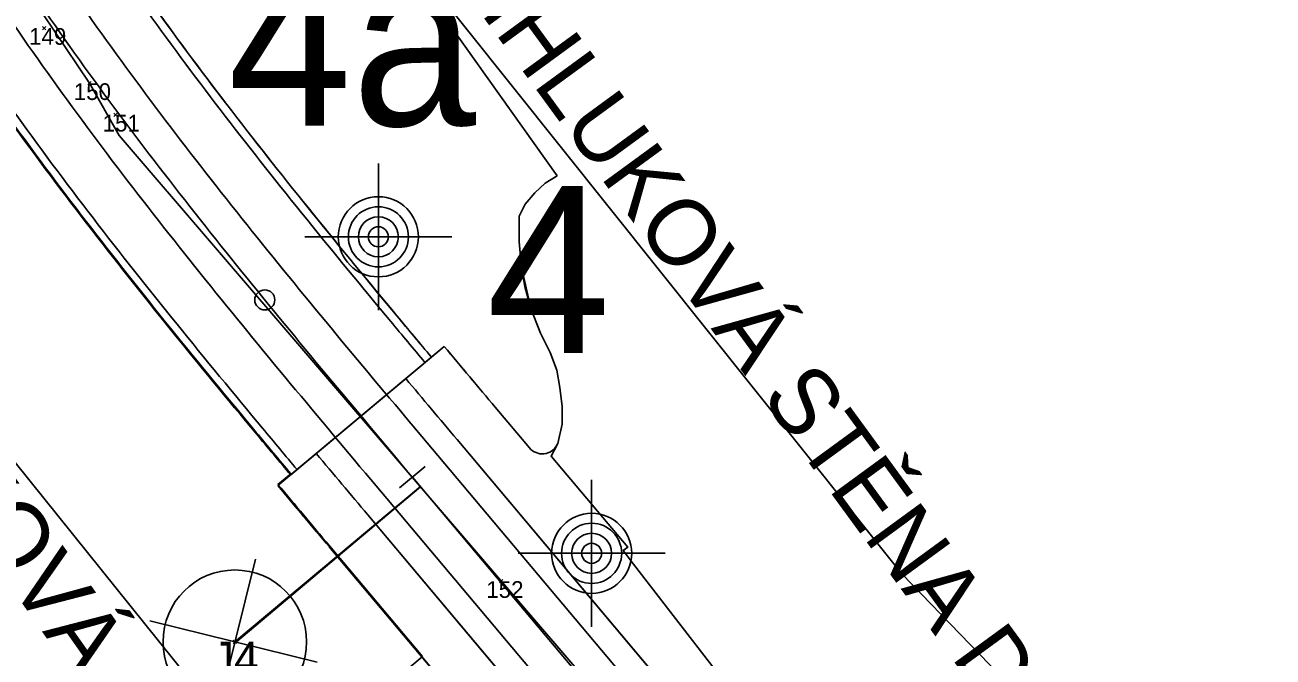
# Model space of a CAD drawing. Extents: x -606444 to -604546, y -1158114 to -1156869.
# Drawn here: x -605089.5 to -605014.7, y -1157408.3 to -1157370.5 of the extents above; entities that cross this region are included whole.
import ezdxf

# ---------------------------------------------------------------- set-up
doc = ezdxf.new("R2010")
doc.units = 0
for name, color, linetype in [('0_sondy', 7, 'Continuous'), ('B_CHOD', 7, 'Continuous'), ('B_TRAM', 7, 'Continuous'), ('B_ZELEN', 7, 'Continuous'), ('geofyzikální profily_předběžný GTP', 7, 'Continuous'), ('jádrové vrty_předběžný GTP', 7, 'Continuous'), ('netisk', 7, 'Continuous'), ('netisk2', 7, 'Continuous'), ('NS_VB', 7, 'Continuous'), ('NS_VB_OBJ', 7, 'Continuous'), ('NS_VB_POP', 7, 'Continuous'), ('OSA', 7, 'Continuous'), ('OSAPOP', 7, 'Continuous'), ('podélný profil trasou tramvaje', 7, 'Continuous'), ('Sondy 2', 7, 'Continuous'), ('sondy současného průzkumu', 7, 'Continuous')]:
    doc.layers.add(name, color=color, linetype=linetype)

# ---------------------------------------------------------------- blocks, each defined once
blk = doc.blocks.new('709')
for p, q in [((0, 2.2), (0, -2.2)), ((-2.2, 0), (2.2, 0))]:
    blk.add_line(p, q)
for radius in [1.2, 0.9, 0.6, 0.3]:
    blk.add_circle((0, 0), radius)
blk = doc.blocks.new('IG vrt podr')
at = {"layer": 'sondy současného průzkumu'}
for p, q in [((0.412, 1.649), (-0.418, -1.672)), ((-1.698, 0.422), (1.644, -0.408))]:
    blk.add_line(p, q, dxfattribs=at)
blk.add_circle((-0.002, 0.001), 1.434, dxfattribs=at)

msp = doc.modelspace()

# ---------------------------------------------------------------- linework, layer by layer
for p, q in [((-605088.39, -1157370.65), (-605088.49, -1157370.55)), ((-605088.39, -1157370.65), (-605088.49, -1157370.75)), ((-605088.39, -1157370.65), (-605088.29, -1157370.55)), ((-605088.39, -1157370.65), (-605088.29, -1157370.75)), ((-605085.67, -1157373.96), (-605085.77, -1157373.86)), ((-605085.67, -1157373.96), (-605085.77, -1157374.06)), ((-605085.67, -1157373.96), (-605085.57, -1157373.86)), ((-605085.67, -1157373.96), (-605085.57, -1157374.06)), ((-605084.1, -1157375.85), (-605084.2, -1157375.75)), ((-605084.1, -1157375.85), (-605084.2, -1157375.95)), ((-605084.1, -1157375.85), (-605084, -1157375.75)), ((-605084.1, -1157375.85), (-605084, -1157375.95)), ((-605060.98, -1157403.8), (-605061.08, -1157403.7)), ((-605060.98, -1157403.8), (-605061.08, -1157403.9)), ((-605060.98, -1157403.8), (-605060.88, -1157403.7)), ((-605060.98, -1157403.8), (-605060.88, -1157403.9)), ((-605076.949, -1157407.435), (-605077.049, -1157407.335)), ((-605076.949, -1157407.435), (-605077.049, -1157407.535)), ((-605076.949, -1157407.435), (-605076.849, -1157407.335)), ((-605076.949, -1157407.435), (-605076.849, -1157407.535))]:
    msp.add_line(p, q)
at = {"layer": 'B_CHOD'}
for points in [[(-605064.406, -1157389.728), (-605065.172, -1157390.37), (-605066.706, -1157391.654)], [(-605059.291, -1157395.814), (-605061.339, -1157393.379)], [(-605063.634, -1157395.311), (-605041.47, -1157421.663), (-605038.896, -1157424.722)], [(-605020.942, -1157444.312), (-605019.149, -1157442.695), (-605022.9, -1157438.91), (-605029, -1157432.1), (-605031.48, -1157429.37), (-605037.89, -1157421.92), (-605043.83, -1157414.58), (-605048.16, -1157409.11), (-605053.06, -1157402.78), (-605053.68, -1157401.97), (-605053.4, -1157401.77), (-605057.995, -1157396.306), (-605057.642, -1157395.638)], [(-605072.072, -1157396.149), (-605074.372, -1157398.075)], [(-605046.828, -1157426.168), (-605068.989, -1157399.819)], [(-605071.29, -1157401.745), (-605049.124, -1157428.099)]]:
    msp.add_lwpolyline(points, dxfattribs=at)
for centre, radius, start, end in [((-602183.251, -1154972.717), 3760.717, 219.993413, 220.066055), ((-603790.648, -1156322.905), 1664.496, 219.947524, 220.111903), ((-605058.526, -1157395.17), 1, 220.06606, 332.12726), ((-603790.638, -1156322.897), 1671.509, 219.947524, 220.111806), ((-603790.638, -1156322.897), 1674.509, 219.947537, 220.111495)]:
    msp.add_arc(centre, radius, start, end, dxfattribs=at)
at = {"layer": 'B_TRAM'}
for p, q in [((-605065.171, -1157390.369), (-605073.604, -1157397.432)), ((-605066.706, -1157391.654), (-605072.072, -1157396.149)), ((-605041.47, -1157421.663), (-605063.634, -1157395.311)), ((-605068.989, -1157399.819), (-605046.828, -1157426.168))]:
    msp.add_line(p, q, dxfattribs=at)
for centre, radius, start, end in [((-604901.683, -1157240.079), 221.711, 215.66934, 217.68438), ((-604798.339, -1157160.25), 352.296, 217.68438, 218.96694), ((-604901.683, -1157240.079), 232.711, 215.66934, 217.68438), ((-604798.339, -1157160.25), 363.296, 217.68438, 218.96694), ((-604687.845, -1157070.879), 494.409, 218.96694, 219.88278), ((-603150.695, -1155786.407), 2497.582, 219.882775, 219.956515), ((-604687.845, -1157070.879), 505.409, 218.96694, 219.88278), ((-603790.648, -1156322.905), 1664.496, 219.947524, 220.111903), ((-603150.695, -1155786.407), 2508.582, 219.882775, 219.956476), ((-603790.638, -1156322.897), 1671.509, 219.947524, 220.111806)]:
    msp.add_arc(centre, radius, start, end, dxfattribs=at)
at = {"layer": 'B_ZELEN'}
for p, q in [((-605067.868, -1157365.11), (-605057.63, -1157379.5)), ((-605058.34, -1157379.94), (-605058.97, -1157380.52)), ((-605057.63, -1157379.5), (-605058.34, -1157379.94)), ((-605058.97, -1157380.52), (-605059.54, -1157381.2)), ((-605059.54, -1157381.2), (-605059.9, -1157381.92)), ((-605059.9, -1157381.92), (-605059.91, -1157383.46)), ((-605059.91, -1157383.46), (-605059.77, -1157384.99)), ((-605059.77, -1157384.99), (-605059.2, -1157387.45)), ((-605059.2, -1157387.45), (-605058.63, -1157388.93)), ((-605058.63, -1157388.93), (-605058.05, -1157390.09)), ((-605064.406, -1157389.728), (-605065.172, -1157390.37)), ((-605058.05, -1157390.09), (-605057.66, -1157391.16)), ((-605057.66, -1157391.16), (-605057.48, -1157392.2)), ((-605057.48, -1157392.2), (-605057.34, -1157393.34)), ((-605059.291, -1157395.814), (-605061.339, -1157393.379)), ((-605057.34, -1157393.34), (-605057.33, -1157394.38)), ((-605057.33, -1157394.38), (-605057.59, -1157395.54)), ((-605057.59, -1157395.54), (-605057.642, -1157395.638)), ((-605073.604, -1157397.358), (-605074.371, -1157398)), ((-605071.284, -1157401.676), (-605065.705, -1157408.309)), ((-605065.705, -1157408.309), (-605068.192, -1157410.401))]:
    msp.add_line(p, q, dxfattribs=at)
for centre, radius, start, end in [((-604892.897, -1157233.535), 232.664, 215.71681, 217.63919), ((-604817.114, -1157175.091), 328.366, 217.63919, 219.01365), ((-604891.215, -1157232.208), 245.76, 215.72279, 217.63087), ((-604820.287, -1157177.526), 335.32, 217.63087, 219.0204), ((-604644.489, -1157035.234), 550.535, 219.01365, 219.83706), ((-603790.638, -1156322.897), 1662.509, 219.837056, 219.947524), ((-604636.207, -1157028.352), 572.254, 219.0204, 219.82928), ((-602183.252, -1154972.717), 3760.716, 219.993413, 220.066055), ((-603948.893, -1156455.108), 1467.246, 219.829284, 219.955291), ((-605058.526, -1157395.17), 1, 220.06606, 332.12805), ((-603790.637, -1156322.822), 1674.509, 219.947524, 220.111765)]:
    msp.add_arc(centre, radius, start, end, dxfattribs=at)
at = {"layer": 'geofyzikální profily_předběžný GTP'}
for points in [[(-605670.777, -1157141.05), (-605656.017, -1157139.471), (-605613.877, -1157139.359), (-605584.802, -1157137.32), (-605531.406, -1157136.329), (-605491.561, -1157133.405), (-605482.073, -1157135.613), (-605438.781, -1157126.664), (-605383.232, -1157124.522), (-605352.341, -1157123.33), (-605321.946, -1157125.999), (-605284.139, -1157130.42), (-605243.303, -1157142.595), (-605207.83, -1157158.833), (-605179.979, -1157186.151), (-605165.292, -1157202.666), (-605149.231, -1157223.341), (-605135.067, -1157244.471), (-605115.915, -1157286.275), (-605103.218, -1157315.843), (-605095.331, -1157330.321), (-605036.966, -1157403.361), (-604999.079, -1157442.536), (-604970.798, -1157468.352)], [(-605668.887, -1157175.563), (-605638.047, -1157172.713), (-605616.091, -1157172.842), (-605512.92, -1157173.16), (-605468.488, -1157175.648), (-605413.499, -1157174.062), (-605313.444, -1157169.44), (-605274.571, -1157178.007), (-605221.389, -1157204.274), (-605178.573, -1157224.003), (-605160.32, -1157243.281), (-605143.644, -1157289.502), (-605117.165, -1157349.927), (-605096.208, -1157389.159), (-605065.898, -1157426.812), (-605053.52, -1157443.58), (-605045.82, -1157465.15), (-605020.205, -1157502.195)]]:
    msp.add_lwpolyline(points, dxfattribs=at)
at = {"layer": 'netisk'}
msp.add_line((-605065.82, -1157398.149), (-605076.95, -1157407.51), dxfattribs=at)
at = {"layer": 'netisk2'}
msp.add_line((-605076.948, -1157407.436), (-605065.831, -1157398.135), dxfattribs=at)
at = {"layer": 'NS_VB'}
for p, q in [((-605067.87, -1157365.11), (-605057.63, -1157379.5)), ((-605058.34, -1157379.94), (-605058.97, -1157380.52)), ((-605057.63, -1157379.5), (-605058.34, -1157379.94)), ((-605058.97, -1157380.52), (-605059.54, -1157381.2)), ((-605059.54, -1157381.2), (-605059.9, -1157381.92)), ((-605059.9, -1157381.92), (-605059.91, -1157383.46)), ((-605059.91, -1157383.46), (-605059.77, -1157384.99)), ((-605059.77, -1157384.99), (-605059.56, -1157386.14)), ((-605059.56, -1157386.14), (-605059.2, -1157387.45)), ((-605059.2, -1157387.45), (-605058.63, -1157388.93)), ((-605058.63, -1157388.93), (-605058.05, -1157390.09)), ((-605066.706, -1157391.654), (-605064.406, -1157389.728)), ((-605058.05, -1157390.09), (-605057.66, -1157391.16)), ((-605057.66, -1157391.16), (-605057.48, -1157392.2)), ((-605057.48, -1157392.2), (-605057.34, -1157393.34)), ((-605057.34, -1157393.34), (-605057.33, -1157394.38)), ((-605057.33, -1157394.38), (-605057.59, -1157395.54)), ((-605057.59, -1157395.54), (-605057.995, -1157396.306)), ((-605074.372, -1157398.075), (-605072.072, -1157396.149)), ((-605053.68, -1157401.97), (-605053.4, -1157401.77)), ((-605053.06, -1157402.78), (-605053.68, -1157401.97)), ((-605053.06, -1157402.78), (-605048.16, -1157409.11))]:
    msp.add_line(p, q, dxfattribs=at)
for points in [[(-605059.291, -1157395.814), (-605061.339, -1157393.379)], [(-605041.47, -1157421.663), (-605063.634, -1157395.311)], [(-605053.4, -1157401.77), (-605057.995, -1157396.306)], [(-605068.989, -1157399.819), (-605046.828, -1157426.168)], [(-605071.285, -1157401.751), (-605049.124, -1157428.099)]]:
    msp.add_lwpolyline(points, dxfattribs=at)
for centre, radius, start, end in [((-604892.799, -1157233.462), 232.786, 215.71506, 217.63866), ((-604892.799, -1157233.462), 233.286, 215.71506, 217.63866), ((-604817.322, -1157175.256), 328.1, 217.63866, 219.01266), ((-604892.799, -1157233.462), 243.786, 215.71506, 217.63866), ((-604817.322, -1157175.256), 328.6, 217.63866, 219.01265), ((-604817.322, -1157175.256), 339.1, 217.63866, 219.01266), ((-604644.516, -1157035.257), 551, 219.01265, 219.83706), ((-604644.516, -1157035.257), 550.5, 219.01266, 219.83706), ((-603790.638, -1156322.897), 1663.009, 219.837056, 219.947524), ((-603790.638, -1156322.897), 1662.509, 219.837056, 219.947524), ((-604644.516, -1157035.257), 561.5, 219.01266, 219.83706), ((-603790.648, -1156322.905), 1661.496, 219.947524, 220.111945), ((-603790.648, -1156322.905), 1664.496, 219.947524, 220.111903), ((-603790.638, -1156322.897), 1673.509, 219.837056, 219.947524), ((-605058.526, -1157395.17), 1, 220.06606, 332.12805), ((-603790.638, -1156322.897), 1671.509, 219.947524, 220.111806), ((-603790.638, -1156322.897), 1674.509, 219.947524, 220.111765)]:
    msp.add_arc(centre, radius, start, end, dxfattribs=at)
at = {"layer": 'NS_VB_OBJ'}
for centre, radius, start, end in [((-604892.799, -1157233.462), 243.286, 215.71506, 217.63866), ((-604817.322, -1157175.256), 338.6, 217.63866, 219.01265), ((-604644.516, -1157035.257), 561, 219.01265, 219.83706), ((-603790.639, -1156322.897), 1673.009, 219.837056, 219.947524)]:
    msp.add_arc(centre, radius, start, end, dxfattribs=at)
at = {"layer": 'OSA'}
msp.add_line((-605044.149, -1157423.916), (-605066.312, -1157397.565), dxfattribs=at)
for points in [[(-605042.618, -1157422.628), (-605064.782, -1157396.277)], [(-605067.842, -1157398.853), (-605045.68, -1157425.203)]]:
    msp.add_lwpolyline(points, dxfattribs=at)
for centre, radius, start, end in [((-604935.793, -1157264.374), 183.333, 213.2421, 215.71506), ((-604935.793, -1157264.374), 185.333, 213.24186, 215.71506), ((-604935.793, -1157264.374), 187.333, 213.24163, 215.71506), ((-604892.799, -1157233.462), 236.286, 215.71506, 217.63866), ((-604892.799, -1157233.462), 238.286, 215.71506, 217.63866), ((-604892.799, -1157233.462), 240.286, 215.71506, 217.63866), ((-604817.322, -1157175.256), 331.6, 217.63866, 219.01266), ((-604817.322, -1157175.256), 333.6, 217.63866, 219.01266), ((-604817.322, -1157175.256), 335.6, 217.63866, 219.01266), ((-604644.516, -1157035.257), 554, 219.01266, 219.83706), ((-604644.516, -1157035.257), 556, 219.01266, 219.83706), ((-604644.516, -1157035.257), 558, 219.01266, 219.83706), ((-603790.648, -1156322.905), 1665.996, 219.837055, 220.111883), ((-603790.648, -1156322.905), 1667.996, 219.837055, 220.111855), ((-603790.638, -1156322.897), 1670.009, 219.837056, 220.111827)]:
    msp.add_arc(centre, radius, start, end, dxfattribs=at)
at = {"layer": 'OSAPOP'}
msp.add_line((-605067.077, -1157398.208), (-605065.546, -1157396.921), dxfattribs=at)
msp.add_circle((-605075.159, -1157386.943), 0.6, dxfattribs=at)
at = {"layer": 'podélný profil trasou tramvaje'}
msp.add_lwpolyline([(-604973.887, -1157496.654), (-605009.522, -1157463.782), (-605083.895, -1157377.089), (-605085.67, -1157373.96), (-605102.483, -1157348.991)], dxfattribs=at)

# ---------------------------------------------------------------- block references
at = {"layer": '0_sondy', "xscale": 2, "yscale": 2}
msp.add_blockref('709', (-605055.563, -1157402.131), dxfattribs=at)
at = {"layer": 'jádrové vrty_předběžný GTP', "xscale": 3, "yscale": 3}
msp.add_blockref('IG vrt podr', (-605076.95, -1157407.434), dxfattribs=at)
at = {"layer": 'Sondy 2', "xscale": 2, "yscale": 2}
msp.add_blockref('709', (-605068.35, -1157383.16), dxfattribs=at)

# ---------------------------------------------------------------- texts
for s, height, p in [('149', 1, (-605089.292, -1157371.65)), ('150', 1, (-605086.611, -1157374.96)), ('151', 1, (-605084.879, -1157376.85)), ('152', 1, (-605061.878, -1157404.8)), ('J4', 2, (-605078.343, -1157409.435))]:
    msp.add_text(s, height=height).set_placement(p)
at = {"layer": '0_sondy'}
msp.add_text('4', height=10, dxfattribs=at).set_placement((-605061.859, -1157390.12))
at = {"layer": 'NS_VB_POP'}
for s, rotation, p in [('NÍZKÁ PROTIHLUKOVÁ STĚNA DL. 46,00 m', 306.15054, (-605081.229, -1157343.767)), ('NÍZKÁ PROTIHLUKOVÁ STĚNA DL. 56,00 m', 305.08639, (-605120.474, -1157361.331))]:
    msp.add_text(s, height=4, rotation=rotation, dxfattribs=at).set_placement(p)
at = {"layer": 'Sondy 2'}
msp.add_text('4a', height=10, dxfattribs=at).set_placement((-605077.37, -1157376.5))

doc.saveas('drawing.dxf')
